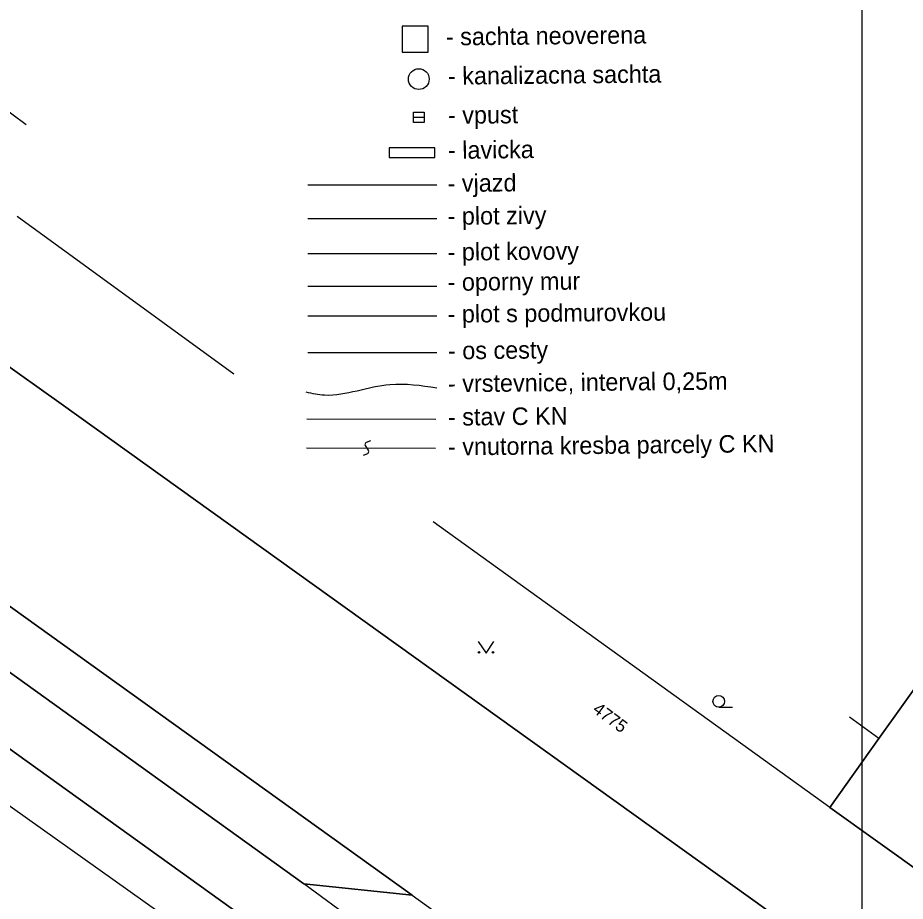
# Model space of a CAD drawing. Extents: x -400488 to -400124, y -1251493 to -1251223.
# Drawn here: x -400282.93 to -400248.76, y -1251313.75 to -1251279.74 of the extents above; entities that cross this region are included whole.
import ezdxf

# ---------------------------------------------------------------- set-up
doc = ezdxf.new("R2010")
doc.units = 0
for name, color, linetype in [('Level 3', 7, 'Continuous'), ('Level 32', 7, 'Continuous'), ('Level 35', 7, 'Continuous'), ('Level 49', 7, 'Continuous'), ('Level 52', 7, 'Continuous'), ('Level 60', 7, 'Continuous'), ('Level 63', 7, 'Continuous')]:
    doc.layers.add(name, color=color, linetype=linetype)

msp = doc.modelspace()

# ---------------------------------------------------------------- linework, layer by layer
at = {"layer": 'Level 3'}
msp.add_lwpolyline([(-400397.431, -1251233.087), (-400250.431, -1251233.087), (-400250.431, -1251440.987), (-400397.431, -1251440.987)], close=True, dxfattribs=at)
at = {"layer": 'Level 32'}
msp.add_lwpolyline([(-400266.795, -1251292.637), (-400271.762, -1251292.637)], dxfattribs=at)
at = {"layer": 'Level 35'}
msp.add_line((-400266.795, -1251286.188), (-400271.762, -1251286.188), dxfattribs=at)
for points in [[(-400271.762, -1251287.468), (-400266.795, -1251287.468)], [(-400271.762, -1251288.819), (-400266.795, -1251288.819)], [(-400271.762, -1251290.07), (-400266.795, -1251290.07)], [(-400266.795, -1251291.222), (-400271.762, -1251291.222)]]:
    msp.add_lwpolyline(points, dxfattribs=at)
at = {"layer": 'Level 49'}
msp.add_spline([(-400266.799, -1251293.993), (-400268.598, -1251293.868), (-400269.867, -1251294.11), (-400271.116, -1251294.272), (-400271.824, -1251294.158)], degree=3, dxfattribs=at)
at = {"layer": 'Level 52'}
msp.add_lwpolyline([(-400267.687, -1251283.57), (-400267.687, -1251283.37), (-400267.287, -1251283.37), (-400267.287, -1251283.57)], dxfattribs=at)
msp.add_lwpolyline([(-400267.687, -1251283.57), (-400267.287, -1251283.57), (-400267.287, -1251283.77), (-400267.687, -1251283.77)], close=True, dxfattribs=at)
msp.add_circle((-400267.487, -1251282.103), 0.4, dxfattribs=at)
at = {"layer": 'Level 60'}
for points in [[(-400268.127, -1251281.062), (-400267.127, -1251281.062), (-400267.127, -1251280.062), (-400268.127, -1251280.062)], [(-400268.626, -1251285.118), (-400266.876, -1251285.117), (-400266.876, -1251284.742), (-400268.626, -1251284.743)]]:
    msp.add_lwpolyline(points, close=True, dxfattribs=at)
at = {"layer": 'Level 63'}
for p, q in [((-400291.07, -1251277.65), (-400282.6, -1251283.85)), ((-400282.95, -1251287.38), (-400274.607, -1251293.448)), ((-400281.26, -1251294.6), (-400285.41, -1251291.65)), ((-400285.41, -1251291.65), (-400281.26, -1251294.6)), ((-400247.51, -1251318.79), (-400281.26, -1251294.6)), ((-400281.26, -1251294.6), (-400247.51, -1251318.79)), ((-400271.805, -1251295.183), (-400266.838, -1251295.193)), ((-400240.99, -1251295.17), (-400249.77, -1251307.48)), ((-400249.77, -1251307.48), (-400240.99, -1251295.17)), ((-400271.807, -1251296.302), (-400266.84, -1251296.312)), ((-400269.551, -1251296.209), (-400269.427, -1251296.409)), ((-400269.346, -1251296.027), (-400269.512, -1251296.092)), ((-400269.466, -1251296.525), (-400269.632, -1251296.591)), ((-400289.76, -1251297.72), (-400267.74, -1251313.52)), ((-400267.74, -1251313.52), (-400289.76, -1251297.72)), ((-400271.92, -1251313.08), (-400290.91, -1251299.42)), ((-400290.91, -1251299.42), (-400271.92, -1251313.08)), ((-400251.66, -1251310.14), (-400266.939, -1251299.15)), ((-400265.2, -1251303.75), (-400264.9, -1251304.2)), ((-400264.9, -1251304.2), (-400264.6, -1251303.75)), ((-400288.16, -1251304.36), (-400263.64, -1251321.96)), ((-400263.64, -1251321.96), (-400288.16, -1251304.36)), ((-400289.15, -1251305.89), (-400264.66, -1251323.25)), ((-400255.94, -1251306.28), (-400255.415, -1251306.28)), ((-400249.77, -1251307.48), (-400250.91, -1251306.66)), ((-400249.77, -1251307.48), (-400250.91, -1251306.66)), ((-400249.77, -1251307.48), (-400251.66, -1251310.14)), ((-400251.66, -1251310.14), (-400249.77, -1251307.48)), ((-400251.66, -1251310.14), (-400232.95, -1251323.57)), ((-400232.95, -1251323.57), (-400251.66, -1251310.14)), ((-400267.74, -1251313.52), (-400271.92, -1251313.08)), ((-400271.92, -1251313.08), (-400267.74, -1251313.52)), ((-400262.45, -1251319.98), (-400271.92, -1251313.08)), ((-400267.74, -1251313.52), (-400261.12, -1251318.24))]:
    msp.add_line(p, q, dxfattribs=at)
for centre, radius in [((-400265.17, -1251304.17), 0.03), ((-400264.63, -1251304.17), 0.03), ((-400255.94, -1251306.055), 0.225)]:
    msp.add_circle(centre, radius, dxfattribs=at)
for centre, start, end in [((-400269.482, -1251296.167), 111.6145, 211.6245), ((-400269.495, -1251296.451), 291.6141, 31.6245)]:
    msp.add_arc(centre, 0.08, start, end, dxfattribs=at)

# ---------------------------------------------------------------- texts
at = {"layer": 'Level 3'}
for s, height, p in [('- sachta neoverena', 0.67392, (-400266.443, -1251280.807)), ('- kanalizacna sachta', 0.67392, (-400266.362, -1251282.317)), ('- vpust', 0.6739, (-400266.362, -1251283.828)), ('- lavicka', 0.6739, (-400266.362, -1251285.174)), ('- vjazd', 0.6739, (-400266.377, -1251286.449)), ('- plot zivy', 0.67392, (-400266.377, -1251287.714)), ('- plot kovovy', 0.67392, (-400266.377, -1251289.093)), ('- oporny mur', 0.67392, (-400266.377, -1251290.254)), ('- plot s podmurovkou', 0.67392, (-400266.377, -1251291.482)), ('- os cesty', 0.6739, (-400266.362, -1251292.892)), ('- vrstevnice, interval 0,25m', 0.67392, (-400266.362, -1251294.159)), ('- stav C KN', 0.67392, (-400266.362, -1251295.444)), ('- vnutorna kresba parcely C KN', 0.67392, (-400266.362, -1251296.589))]:
    msp.add_text(s, height=height, rotation=0.5734, dxfattribs=at).set_placement(p)
at = {"layer": 'Level 63'}
msp.add_text('4775', height=0.48, rotation=323.1561, dxfattribs=at).set_placement((-400260.828, -1251306.441))

doc.saveas('drawing.dxf')
